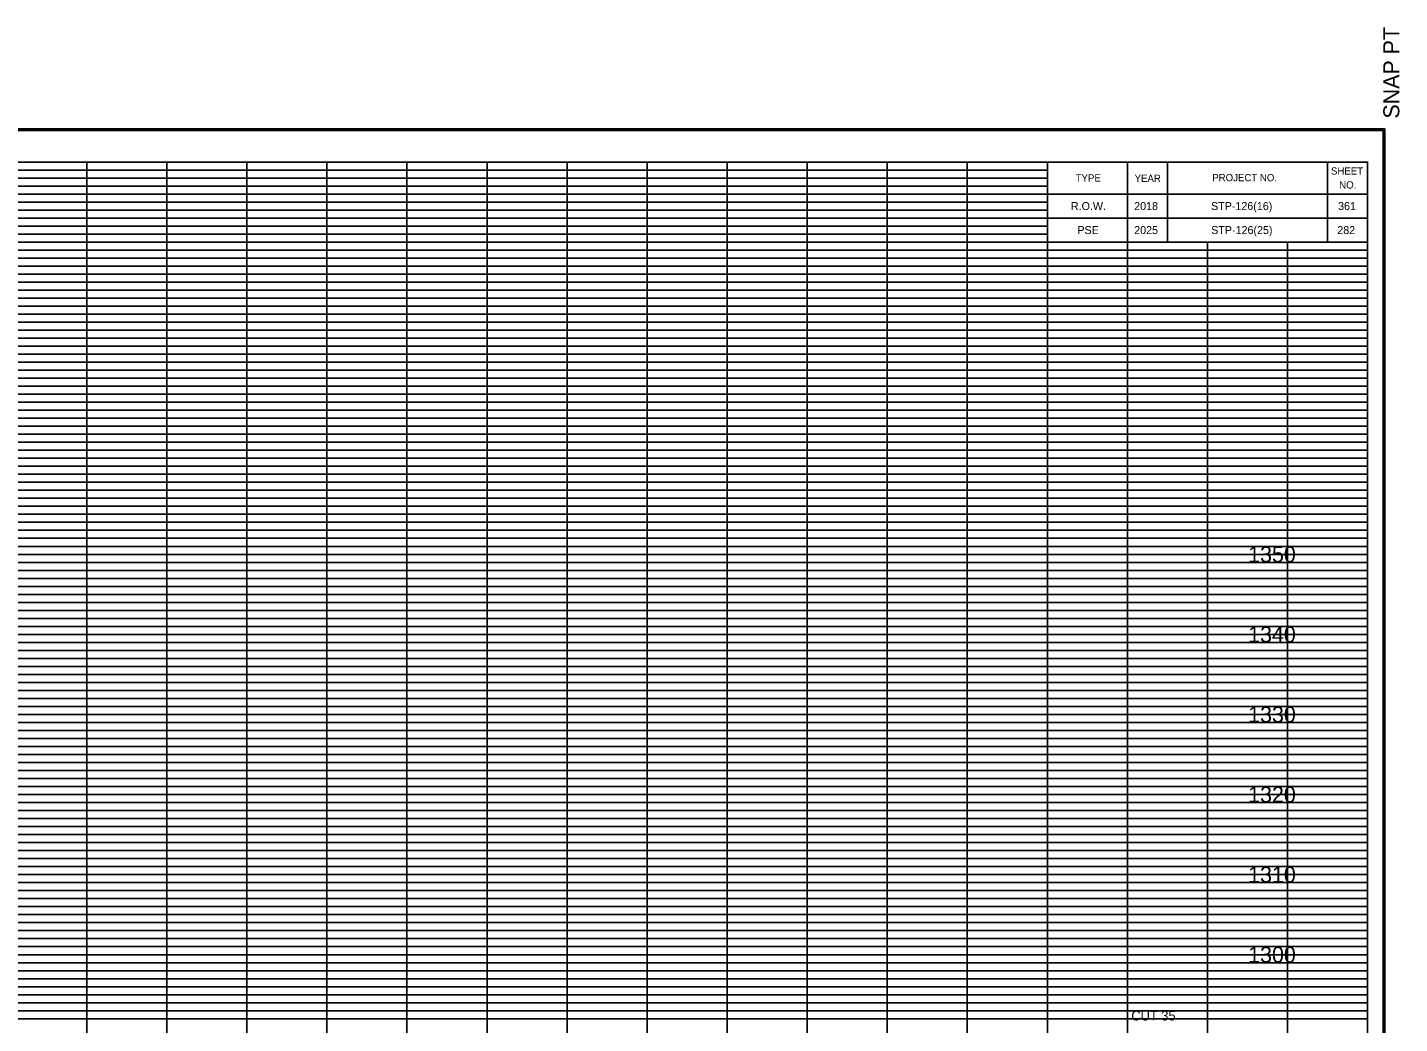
# Model space of a CAD drawing. Extents: x 980 to 1324, y 978 to 2847.
# Drawn here: x 1152.6 to 1324, y 2182.4 to 2306.8 of the extents above; entities that cross this region are included whole.
import ezdxf

# ---------------------------------------------------------------- set-up
doc = ezdxf.new("R2010")
doc.units = 0
for name, color, linetype in [('DESIGN - SCRATCH - User 1', 7, 'Continuous'), ('DESIGN - SHEET - Corner Text', 7, 'Continuous'), ('DESIGN - SHEET - Light Grid', 7, 'Continuous'), ('DESIGN - SHEET - Linework', 7, 'Continuous'), ('DESIGN - SHEET - Plot Shape', 7, 'Continuous'), ('DESIGN - TYPICAL - Text', 7, 'Continuous')]:
    doc.layers.add(name, color=color, linetype=linetype)

# ---------------------------------------------------------------- blocks, each defined once
blk = doc.blocks.new('XSTSHT')
at = {"layer": 'DESIGN - SCRATCH - User 1'}
for p, q in [((28.5, 20.45), (28.5, 20.45)), ((29.24, 20.45), (29.24, 20.45)), ((30.49, 20.45), (30.49, 20.45)), ((31.74, 20.45), (31.74, 20.45)), ((28.5, 20.15), (28.5, 20.15)), ((29.24, 20.15), (29.24, 20.15)), ((30.49, 20.15), (30.49, 20.15)), ((31.74, 20.15), (31.74, 20.15))]:
    blk.add_line(p, q, dxfattribs=at)
at = {"layer": 'DESIGN - SHEET - Light Grid'}
for p, q in [((8, 20.9), (16, 20.9)), ((8, 20.8), (16, 20.8)), ((16, 20.9), (24, 20.9)), ((16, 20.8), (24, 20.8)), ((24, 20.9), (28, 20.9)), ((24, 20.8), (28, 20.8)), ((8, 20.7), (16, 20.7)), ((8, 20.6), (16, 20.6)), ((16, 20.7), (24, 20.7)), ((16, 20.6), (24, 20.6)), ((24, 20.7), (28, 20.7)), ((24, 20.6), (28, 20.6)), ((8, 20.5), (16, 20.5)), ((8, 20.4), (16, 20.4)), ((16, 20.5), (24, 20.5)), ((16, 20.4), (24, 20.4)), ((24, 20.5), (28, 20.5)), ((24, 20.4), (28, 20.4)), ((8, 20.3), (16, 20.3)), ((16, 20.3), (24, 20.3)), ((24, 20.3), (28, 20.3)), ((8, 20.2), (16, 20.2)), ((8, 20.1), (16, 20.1)), ((16, 20.2), (24, 20.2)), ((16, 20.1), (24, 20.1)), ((24, 20.2), (28, 20.2)), ((24, 20.1), (28, 20.1)), ((8, 19.9), (16, 19.9)), ((16, 19.9), (24, 19.9)), ((24, 19.9), (32, 19.9)), ((8, 19.8), (16, 19.8)), ((16, 19.8), (24, 19.8)), ((24, 19.8), (32, 19.8)), ((8, 19.7), (16, 19.7)), ((8, 19.6), (16, 19.6)), ((16, 19.7), (24, 19.7)), ((16, 19.6), (24, 19.6)), ((24, 19.7), (32, 19.7)), ((24, 19.6), (32, 19.6)), ((8, 19.5), (16, 19.5)), ((8, 19.4), (16, 19.4)), ((16, 19.5), (24, 19.5)), ((16, 19.4), (24, 19.4)), ((24, 19.5), (32, 19.5)), ((24, 19.4), (32, 19.4)), ((8, 19.3), (16, 19.3)), ((8, 19.2), (16, 19.2)), ((16, 19.3), (24, 19.3)), ((16, 19.2), (24, 19.2)), ((24, 19.3), (32, 19.3)), ((24, 19.2), (32, 19.2)), ((8, 19.1), (16, 19.1)), ((16, 19.1), (24, 19.1)), ((24, 19.1), (32, 19.1)), ((8, 18.9), (16, 18.9)), ((16, 18.9), (24, 18.9)), ((24, 18.9), (32, 18.9)), ((8, 18.8), (16, 18.8)), ((8, 18.7), (16, 18.7)), ((16, 18.8), (24, 18.8)), ((16, 18.7), (24, 18.7)), ((24, 18.8), (32, 18.8)), ((24, 18.7), (32, 18.7)), ((8, 18.6), (16, 18.6)), ((16, 18.6), (24, 18.6)), ((24, 18.6), (32, 18.6)), ((8, 18.5), (16, 18.5)), ((8, 18.4), (16, 18.4)), ((16, 18.5), (24, 18.5)), ((16, 18.4), (24, 18.4)), ((24, 18.5), (32, 18.5)), ((24, 18.4), (32, 18.4)), ((8, 18.3), (16, 18.3)), ((8, 18.2), (16, 18.2)), ((16, 18.3), (24, 18.3)), ((16, 18.2), (24, 18.2)), ((24, 18.3), (32, 18.3)), ((24, 18.2), (32, 18.2)), ((8, 18.1), (16, 18.1)), ((16, 18.1), (24, 18.1)), ((24, 18.1), (32, 18.1)), ((8, 17.9), (16, 17.9)), ((16, 17.9), (24, 17.9)), ((24, 17.9), (32, 17.9)), ((8, 17.8), (16, 17.8)), ((8, 17.7), (16, 17.7)), ((16, 17.8), (24, 17.8)), ((16, 17.7), (24, 17.7)), ((24, 17.8), (32, 17.8)), ((24, 17.7), (32, 17.7)), ((8, 17.6), (16, 17.6)), ((8, 17.5), (16, 17.5)), ((16, 17.6), (24, 17.6)), ((16, 17.5), (24, 17.5)), ((24, 17.6), (32, 17.6)), ((24, 17.5), (32, 17.5)), ((8, 17.4), (16, 17.4)), ((16, 17.4), (24, 17.4)), ((24, 17.4), (32, 17.4)), ((8, 17.3), (16, 17.3)), ((8, 17.2), (16, 17.2)), ((16, 17.3), (24, 17.3)), ((16, 17.2), (24, 17.2)), ((24, 17.3), (32, 17.3)), ((24, 17.2), (32, 17.2)), ((8, 17.1), (16, 17.1)), ((16, 17.1), (24, 17.1)), ((24, 17.1), (32, 17.1)), ((8, 16.9), (16, 16.9)), ((8, 16.8), (16, 16.8)), ((16, 16.9), (24, 16.9)), ((16, 16.8), (24, 16.8)), ((24, 16.9), (32, 16.9)), ((24, 16.8), (32, 16.8)), ((8, 16.7), (16, 16.7)), ((16, 16.7), (24, 16.7)), ((24, 16.7), (32, 16.7)), ((8, 16.6), (16, 16.6)), ((8, 16.5), (16, 16.5)), ((16, 16.6), (24, 16.6)), ((16, 16.5), (24, 16.5)), ((24, 16.6), (32, 16.6)), ((24, 16.5), (32, 16.5)), ((8, 16.4), (16, 16.4)), ((8, 16.3), (16, 16.3)), ((16, 16.4), (24, 16.4)), ((16, 16.3), (24, 16.3)), ((24, 16.4), (32, 16.4)), ((24, 16.3), (32, 16.3)), ((8, 16.2), (16, 16.2)), ((16, 16.2), (24, 16.2)), ((24, 16.2), (32, 16.2)), ((8, 16.1), (16, 16.1)), ((16, 16.1), (24, 16.1)), ((24, 16.1), (32, 16.1)), ((8, 15.9), (16, 15.9)), ((8, 15.8), (16, 15.8)), ((16, 15.9), (24, 15.9)), ((16, 15.8), (24, 15.8)), ((24, 15.9), (32, 15.9)), ((24, 15.8), (32, 15.8)), ((8, 15.7), (16, 15.7)), ((8, 15.6), (16, 15.6)), ((16, 15.7), (24, 15.7)), ((16, 15.6), (24, 15.6)), ((24, 15.7), (32, 15.7)), ((24, 15.6), (32, 15.6)), ((8, 15.5), (16, 15.5)), ((16, 15.5), (24, 15.5)), ((24, 15.5), (32, 15.5)), ((8, 15.4), (16, 15.4)), ((8, 15.3), (16, 15.3)), ((16, 15.4), (24, 15.4)), ((16, 15.3), (24, 15.3)), ((24, 15.4), (32, 15.4)), ((24, 15.3), (32, 15.3)), ((8, 15.2), (16, 15.2)), ((8, 15.1), (16, 15.1)), ((16, 15.2), (24, 15.2)), ((16, 15.1), (24, 15.1)), ((24, 15.2), (32, 15.2)), ((24, 15.1), (32, 15.1)), ((8, 14.9), (16, 14.9)), ((8, 14.8), (16, 14.8)), ((16, 14.9), (24, 14.9)), ((16, 14.8), (24, 14.8)), ((24, 14.9), (32, 14.9)), ((24, 14.8), (32, 14.8)), ((8, 14.7), (16, 14.7)), ((8, 14.6), (16, 14.6)), ((16, 14.7), (24, 14.7)), ((16, 14.6), (24, 14.6)), ((24, 14.7), (32, 14.7)), ((24, 14.6), (32, 14.6)), ((8, 14.5), (16, 14.5)), ((8, 14.4), (16, 14.4)), ((16, 14.5), (24, 14.5)), ((16, 14.4), (24, 14.4)), ((24, 14.5), (32, 14.5)), ((24, 14.4), (32, 14.4)), ((8, 14.3), (16, 14.3)), ((16, 14.3), (24, 14.3)), ((24, 14.3), (32, 14.3)), ((8, 14.2), (16, 14.2)), ((8, 14.1), (16, 14.1)), ((16, 14.2), (24, 14.2)), ((16, 14.1), (24, 14.1)), ((24, 14.2), (32, 14.2)), ((24, 14.1), (32, 14.1)), ((8, 13.9), (16, 13.9)), ((16, 13.9), (24, 13.9)), ((24, 13.9), (32, 13.9)), ((8, 13.8), (16, 13.8)), ((16, 13.8), (24, 13.8)), ((24, 13.8), (32, 13.8)), ((8, 13.7), (16, 13.7)), ((8, 13.6), (16, 13.6)), ((16, 13.7), (24, 13.7)), ((16, 13.6), (24, 13.6)), ((24, 13.7), (32, 13.7)), ((24, 13.6), (32, 13.6)), ((8, 13.5), (16, 13.5)), ((8, 13.4), (16, 13.4)), ((16, 13.5), (24, 13.5)), ((16, 13.4), (24, 13.4)), ((24, 13.5), (32, 13.5)), ((24, 13.4), (32, 13.4)), ((8, 13.3), (16, 13.3)), ((8, 13.2), (16, 13.2)), ((16, 13.3), (24, 13.3)), ((16, 13.2), (24, 13.2)), ((24, 13.3), (32, 13.3)), ((24, 13.2), (32, 13.2)), ((8, 13.1), (16, 13.1)), ((16, 13.1), (24, 13.1)), ((24, 13.1), (32, 13.1)), ((8, 12.9), (16, 12.9)), ((16, 12.9), (24, 12.9)), ((24, 12.9), (32, 12.9)), ((8, 12.8), (16, 12.8)), ((8, 12.7), (16, 12.7)), ((16, 12.8), (24, 12.8)), ((16, 12.7), (24, 12.7)), ((24, 12.8), (32, 12.8)), ((24, 12.7), (32, 12.7)), ((8, 12.6), (16, 12.6)), ((16, 12.6), (24, 12.6)), ((24, 12.6), (32, 12.6)), ((8, 12.5), (16, 12.5)), ((8, 12.4), (16, 12.4)), ((16, 12.5), (24, 12.5)), ((16, 12.4), (24, 12.4)), ((24, 12.5), (32, 12.5)), ((24, 12.4), (32, 12.4)), ((8, 12.3), (16, 12.3)), ((8, 12.2), (16, 12.2)), ((16, 12.3), (24, 12.3)), ((16, 12.2), (24, 12.2)), ((24, 12.3), (32, 12.3)), ((24, 12.2), (32, 12.2)), ((8, 12.1), (16, 12.1)), ((16, 12.1), (24, 12.1)), ((24, 12.1), (32, 12.1)), ((8, 11.9), (16, 11.9)), ((16, 11.9), (24, 11.9)), ((24, 11.9), (32, 11.9)), ((8, 11.8), (16, 11.8)), ((8, 11.7), (16, 11.7)), ((16, 11.8), (24, 11.8)), ((16, 11.7), (24, 11.7)), ((24, 11.8), (32, 11.8)), ((24, 11.7), (32, 11.7)), ((8, 11.6), (16, 11.6)), ((8, 11.5), (16, 11.5)), ((16, 11.6), (24, 11.6)), ((16, 11.5), (24, 11.5)), ((24, 11.6), (32, 11.6)), ((24, 11.5), (32, 11.5)), ((8, 11.4), (16, 11.4)), ((16, 11.4), (24, 11.4)), ((24, 11.4), (32, 11.4)), ((8, 11.3), (16, 11.3)), ((8, 11.2), (16, 11.2)), ((16, 11.3), (24, 11.3)), ((16, 11.2), (24, 11.2)), ((24, 11.3), (32, 11.3)), ((24, 11.2), (32, 11.2)), ((8, 11.1), (16, 11.1)), ((16, 11.1), (24, 11.1)), ((24, 11.1), (32, 11.1)), ((8, 10.9), (16, 10.9)), ((8, 10.8), (16, 10.8)), ((16, 10.9), (24, 10.9)), ((16, 10.8), (24, 10.8)), ((24, 10.9), (32, 10.9)), ((24, 10.8), (32, 10.8)), ((8, 10.7), (16, 10.7)), ((16, 10.7), (24, 10.7)), ((24, 10.7), (32, 10.7)), ((8, 10.6), (16, 10.6)), ((8, 10.5), (16, 10.5)), ((16, 10.6), (24, 10.6)), ((16, 10.5), (24, 10.5)), ((24, 10.6), (32, 10.6)), ((24, 10.5), (32, 10.5)), ((8, 10.4), (16, 10.4)), ((8, 10.3), (16, 10.3)), ((16, 10.4), (24, 10.4)), ((16, 10.3), (24, 10.3)), ((24, 10.4), (32, 10.4)), ((24, 10.3), (32, 10.3))]:
    blk.add_line(p, q, dxfattribs=at)
at = {"layer": 'DESIGN - SHEET - Linework'}
for p, q in [((-1.823, 21.414), (32.217, 21.414)), ((32.217, 21.414), (32.217, -0.414)), ((16, 0), (16, 21)), ((17, 0), (17, 21)), ((18, 0), (18, 21)), ((19, 0), (19, 21)), ((20, 0), (20, 21)), ((21, 0), (21, 21)), ((22, 0), (22, 21)), ((23, 0), (23, 21)), ((24, 0), (24, 21)), ((25, 0), (25, 21)), ((26, 0), (26, 21)), ((27, 0), (27, 21)), ((0, 20), (28, 20)), ((28, 0), (28, 20)), ((29, 0), (29, 20)), ((30, 0), (30, 20)), ((31, 0), (31, 20)), ((0, 19), (32, 19)), ((0, 18), (32, 18)), ((0, 17), (32, 17)), ((0, 16), (32, 16)), ((0, 15), (32, 15)), ((0, 14), (32, 14)), ((0, 13), (32, 13)), ((0, 12), (32, 12)), ((0, 11), (32, 11))]:
    blk.add_line(p, q, dxfattribs=at)
for points in [[(0, 21), (0, 0), (32, 0), (32, 21), (0, 21)], [(28, 21), (28, 20), (32, 20), (32, 21), (31.5, 21), (31.5, 20), (29.5, 20), (29.5, 21), (29, 21), (29, 20), (32, 20), (28, 20), (28, 20.3), (32, 20.3), (32, 20.6), (28, 20.6)]]:
    blk.add_lwpolyline(points, dxfattribs=at)
at = {"layer": 'DESIGN - SHEET - Plot Shape'}
for points in [[(-1.803, 21.394), (32.197, 21.394), (32.197, -0.394), (-1.803, -0.394)], [(-0.85, 21), (32, 21), (32, -0.25), (-0.85, -0.25)]]:
    blk.add_lwpolyline(points, close=True, dxfattribs=at)
at = {"layer": 'DESIGN - SHEET - Corner Text'}
blk.add_text('  SNAP PT', height=0.2, rotation=90, dxfattribs=at).set_placement((32.397, 21.394))
for s, p in [('SHEET', (31.543, 20.843)), ('TYPE', (28.354, 20.756)), ('YEAR', (29.09, 20.752)), ('PROJECT NO.', (30.06, 20.76)), ('NO.', (31.646, 20.669))]:
    blk.add_text(s, height=0.09, dxfattribs=at).set_placement(p)

msp = doc.modelspace()

# ---------------------------------------------------------------- linework, layer by layer
at = {"layer": 'DESIGN - SHEET - Plot Shape'}
msp.add_lwpolyline([(991.5, 2077.5), (1320, 2077.5), (1320, 2290), (991.5, 2290)], close=True, dxfattribs=at)

# ---------------------------------------------------------------- block references
at = {"layer": 'DESIGN - SHEET - Plot Shape', "xscale": 10, "yscale": 10}
msp.add_blockref('XSTSHT', (1000, 2080), dxfattribs=at)

# ---------------------------------------------------------------- texts
at = {"layer": 'DESIGN - SHEET - Corner Text'}
for s, p in [('R.O.W.', (1282.94, 2284)), ('2018', (1290.85, 2284)), ('STP-126(16)', (1300.45, 2284)), ('361', (1316.32, 2284)), ('PSE', (1283.75, 2281)), ('2025', (1290.85, 2281)), ('STP-126(25)', (1300.47, 2281)), ('282', (1316.22, 2281))]:
    msp.add_text(s, height=1, dxfattribs=at).set_placement(p)
at = {"layer": 'DESIGN - TYPICAL - Text'}
for s, height, p in [('     1350     ', 2, (1301.37, 2240)), ('     1340     ', 2, (1301.37, 2230)), ('     1330     ', 2, (1301.37, 2220)), ('     1320     ', 2, (1301.37, 2210)), ('     1310     ', 2, (1301.37, 2200)), ('     1300     ', 2, (1301.37, 2190)), ('CUT 35', 1.2, (1290.49, 2182.78))]:
    msp.add_text(s, height=height, dxfattribs=at).set_placement(p)

doc.saveas('drawing.dxf')
